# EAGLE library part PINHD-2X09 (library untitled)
PIN HEADER
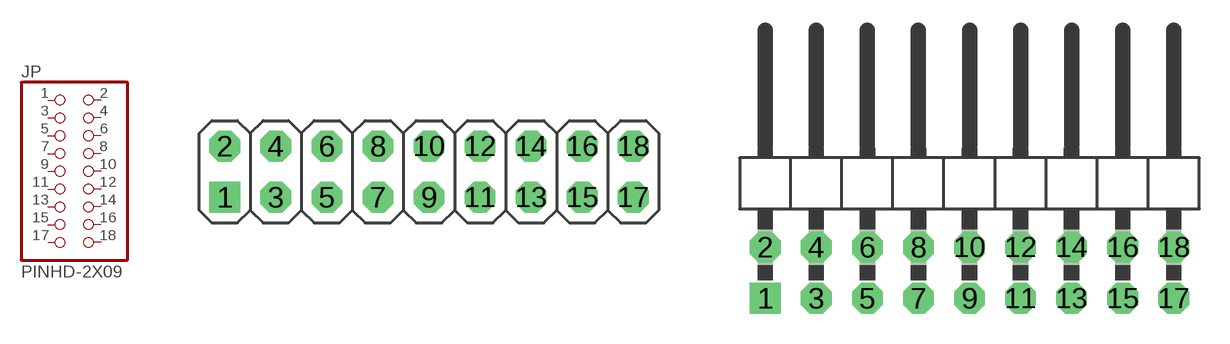
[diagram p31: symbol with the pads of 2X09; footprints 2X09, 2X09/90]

Designator prefix JP

## PINHD-2X09_2.54  [2X09]
1  1  pas
2  2  pas
3  3  pas
4  4  pas
5  5  pas
6  6  pas
7  7  pas
8  8  pas
9  9  pas
10  10  pas
11  11  pas
12  12  pas
13  13  pas
14  14  pas
15  15  pas
16  16  pas
17  17  pas
18  18  pas

## PINHD-2X09_2.54-90°  [2X09/90]
Pads as for 2X09

## PINHD-2X09_2.00  [2X09M]
Pads as for 2X09

## PINHD-2X09_2.54-SMD  [2X09SMD]
Pads as for 2X09

## PINHD-2X09_MICROMATCH  [MICROMATCH-18]
Pads as for 2X09

## PINHD-2X09_2.54-SMD-90°  [2X09SMD/90]
Pads as for 2X09

## Footprint 2X09 (pad centres in mm)
PIN HEADER - 2.54
drill 1.016 square: 1 -10.16,-1.27
drill 1.016 octagon: 2 -10.16,1.27; 3 -7.62,-1.27; 4 -7.62,1.27; 5 -5.08,-1.27; 6 -5.08,1.27; 7 -2.54,-1.27; 8 -2.54,1.27; 9 0,-1.27; 10 0,1.27; 11 2.54,-1.27; 12 2.54,1.27; 13 5.08,-1.27; 14 5.08,1.27; 15 7.62,-1.27; 16 7.62,1.27; 17 10.16,-1.27; 18 10.16,1.27

## Footprint 2X09/90 (pad centres in mm)
PIN HEADER - 2.54 90°
drill 1.016 square: 1 -10.16,-6.35
drill 1.016 octagon: 2 -10.16,-3.81; 3 -7.62,-6.35; 4 -7.62,-3.81; 5 -5.08,-6.35; 6 -5.08,-3.81; 7 -2.54,-6.35; 8 -2.54,-3.81; 9 0,-6.35; 10 0,-3.81; 11 2.54,-6.35; 12 2.54,-3.81; 13 5.08,-6.35; 14 5.08,-3.81; 15 7.62,-6.35; 16 7.62,-3.81; 17 10.16,-6.35; 18 10.16,-3.81

## Footprint 2X09M (pad centres in mm)
PIN HEADER - 2
drill 0.914 square: 1 -8,-1
drill 0.914 round: 2 -8,1; 3 -6,-1; 4 -6,1; 5 -4,-1; 6 -4,1; 7 -2,-1; 8 -2,1; 9 0,-1; 10 0,1; 11 2,-1; 12 2,1; 13 4,-1; 14 4,1; 15 6,-1; 16 6,1; 17 8,-1; 18 8,1

## Footprint 2X09SMD (pad centres in mm)
PIN HEADER - 2.54 SMD
smd 1.016 x 3.302: 1 -1.27,-3.81; 2 -1.27,1.27; 3 1.27,-3.81; 4 1.27,1.27; 5 3.81,-3.81; 6 3.81,1.27; 7 6.35,-3.81; 8 6.35,1.27; 9 8.89,-3.81; 10 8.89,1.27; 11 11.43,-3.81; 12 11.43,1.27; 13 13.97,-3.81; 14 13.97,1.27; 15 16.51,-3.81; 16 16.51,1.27; 17 19.05,-3.81; 18 19.05,1.27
